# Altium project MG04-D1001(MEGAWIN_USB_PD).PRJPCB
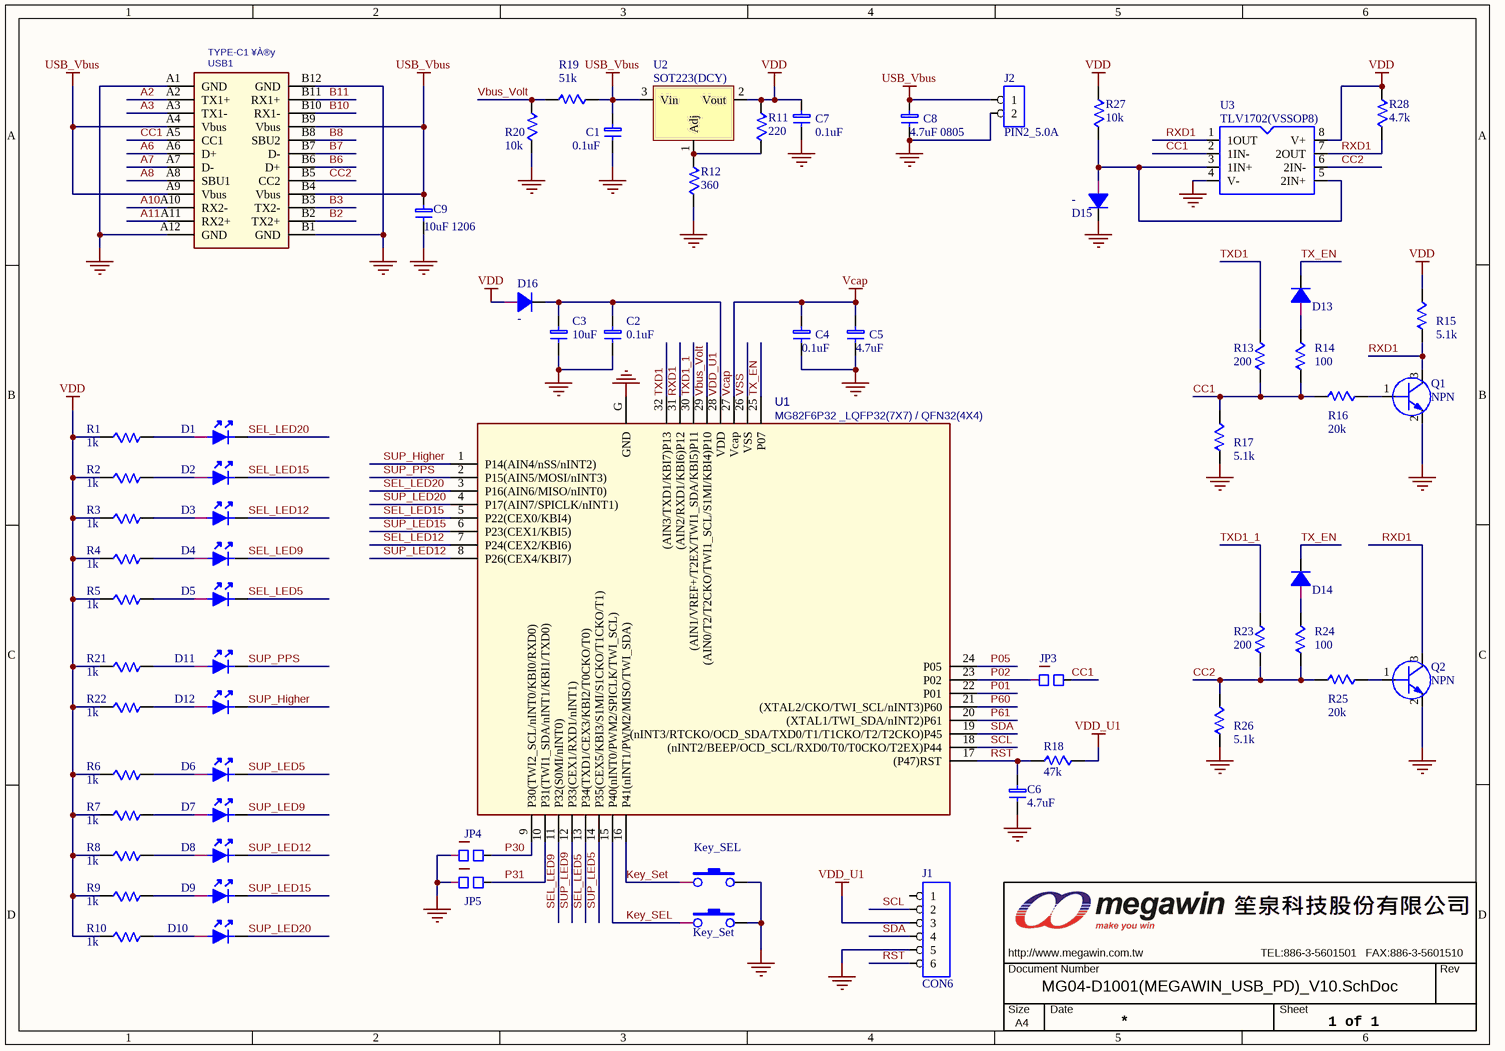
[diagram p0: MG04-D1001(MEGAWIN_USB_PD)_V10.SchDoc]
1 sheet, 67 parts. Net scope: global (net labels, ports and power ports of the same name join across sheets).
Board file: MG04-D1001(MEGAWIN_USB_PD)_V10.PcbDoc

## Sheet MG04-D1001(MEGAWIN_USB_PD)_V10.SchDoc
size 279 x 195 mm

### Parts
C1  0.1uF  [0603C]
C2  0.1uF  [0603C]
C3  10uF  [0603C]
C4  0.1uF  [0603C]
C5  4.7uF  [0603C]
C6  4.7uF  [0603C]
C7  0.1uF  [0603C]
C8  4.7uF 0805  [0805C]
C9  10uF 1206  [1206C]
D1  LED_SC  [0603D]  (value not drawn)
D2  LED_SC  [0603D]  (value not drawn)
D3  LED_SC  [0603D]  (value not drawn)
D4  LED_SC  [0603D]  (value not drawn)
D5  LED_SC  [0603D]  (value not drawn)
D6  LED_SC  [0603D]  (value not drawn)
D7  LED_SC  [0603D]  (value not drawn)
D8  LED_SC  [0603D]  (value not drawn)
D9  LED_SC  [0603D]  (value not drawn)
D10  LED_SC  [0603D]  (value not drawn)
D11  LED_SC  [0603D]  (value not drawn)
D12  LED_SC  [0603D]  (value not drawn)
D13  1N5817  [D4148_SMD]  (value not drawn)
D14  1N5817  [D4148_SMD]  (value not drawn)
D15  -  [D4148_SMD]
D16  -  [D4148_SMD]
J1  CON6  [PS6P254]
J2  PIN2_5.0A  [PIN2_5.0A]
JP3  JUMPER_2  [0603J]  (value not drawn)
JP4  JUMPER_2  [0603J]  (value not drawn)
JP5  JUMPER_2  [0603J]  (value not drawn)
Key_SEL  SW-PB  [SW_T]  (value not drawn)
Key_Set  SW-PB  [SW_T]  (value not drawn)
MW1  OrgAddr3: TEL:886-3-5601501   FAX:886-3-5601510  Page Size: A4  [MEGAWIN_3.4_LOGO]  (hidden comment: MW-A4)  (no BOM)
Q1  NPN  [SOT23]
Q2  NPN  [SOT23]
R1  1k  [0603R]
R2  1k  [0603R]
R3  1k  [0603R]
R4  1k  [0603R]
R5  1k  [0603R]
R6  1k  [0603R]
R7  1k  [0603R]
R8  1k  [0603R]
R9  1k  [0603R]
R10  1k  [0603R]
R11  220  [0603R]
R12  360  [0603R]
R13  200  [0603R]
R14  100  [0603R]
R15  5.1k  [0603R]
R16  20k  [0603R]
R17  5.1k  [0603R]
R18  47k  [0603R]
R19  51k  [0603R]
R20  10k  [0603R]
R21  1k  [0603R]
R22  1k  [0603R]
R23  200  [0603R]
R24  100  [0603R]
R25  20k  [0603R]
R26  5.1k  [0603R]
R27  10k  [0603R]
R28  4.7k  [0603R]
U1  MG82F6P32 _LQFP32(7X7) / QFN32(4X4)  [QFP32_7X7_QFN32_4X4]
U2  SOT223(DCY)  [SOT223]
U3  TLV1702(VSSOP8)  [SO8_120P065]
USB1  TYPE-C1 ¥À®y  [USB24_CF]

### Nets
USB_Vbus: C1.1 C8.1 C9.1 J2.1 R19.2 U2.3(Vin) USB1.A4(Vbus) USB1.A9(Vbus) USB1.B4(Vbus) USB1.B9(Vbus)
Vcap: C4.1 C5.1 U1.27(Vcap)
VDD: C7.1 D16.1(A) R1.2 R2.2 R3.2 R4.2 R5.2 R6.2 R7.2 R8.2 R9.2 R10.2 R11.1 R15.2 R21.2 R22.2 R27.1 R28.1 U2.2(Vout) U3.8(V+)
VDD_U1: C2.1 C3.1 D16.2(K) J1.3 R18.2 U1.28(VDD)
VSS: C1.2 C2.2 C3.2 C4.2 C5.2 C6.2 C7.2 C8.2 C9.2 D15.2(K) J1.5 J2.2 JP4.1 JP5.1 Key_SEL.2 Key_Set.2 Q1.2(E) Q2.2(E) R12.2 R17.1 R20.2 R26.1 U1.26(VSS) U1.G(GND) U3.4(V-) USB1.A1(GND) USB1.A12(GND) USB1.B1(GND) USB1.B12(GND)
A2: USB1.A2(TX1+)
A3: USB1.A3(TX1-)
A6: USB1.A6(D+)
A7: USB1.A7(D-)
A8: USB1.A8(SBU1)
A10: USB1.A10(RX2-)
A11: USB1.A11(RX2+)
B2: USB1.B2(TX2+)
B3: USB1.B3(TX2-)
B6: USB1.B6(D+)
B7: USB1.B7(D-)
B8: USB1.B8(SBU2)
B10: USB1.B10(RX1-)
B11: USB1.B11(RX1+)
CC1: JP3.2 R13.1 R14.1 R16.1 R17.2 U3.2(1IN-) USB1.A5(CC1)
CC2: R23.1 R24.1 R25.1 R26.2 U3.6(2IN-) USB1.B5(CC2)
Key_SEL: Key_Set.1 U1.15(P40(nINT0/PWM2/SPICLK/TWI_SCL))
Key_Set: Key_SEL.1 U1.16(P41(nINT1/PWM2/MISO/TWI_SDA))
P01: U1.22(P01)
P02: JP3.1 U1.23(P02)
P05: U1.24(P05)
P30: JP4.2 U1.9(P30(TWI2_SCL/nINT0/KBI0/RXD0))
P31: JP5.2 U1.10(P31(TWI1_SDA/nINT1/KBI1/TXD0))
P60: U1.21((XTAL2/CKO/TWI_SCL/nINT3)P60)
P61: U1.20((XTAL1/TWI_SDA/nINT2)P61)
RST: C6.1 J1.6 R18.1 U1.17((P47)RST)
RXD1: Q1.3(C) Q2.3(C) R15.1 R28.2 U1.31((AIN2/RXD1/KBI6)P12) U3.1(1OUT) U3.7(2OUT)
SCL: J1.2 U1.18((nINT2/BEEP/OCD_SCL/RXD0/T0/T0CKO/T2EX)P44)
SDA: J1.4 U1.19((nINT3/RTCKO/OCD_SDA/TXD0/T1/T1CKO/T2/T2CKO)P45)
SEL_LED5: D5.2 U1.13(P34(TXD1/CEX3/KBI2/T0CKO/T0))
SEL_LED9: D4.2 U1.11(P32(S0MI/nINT0))
SEL_LED12: D3.2 U1.7(P24(CEX2/KBI6))
SEL_LED15: D2.2 U1.5(P22(CEX0/KBI4))
SEL_LED20: D1.2 U1.3(P16(AIN6/MISO/nINT0))
SUP_Higher: D12.2 U1.1(P14(AIN4/nSS/nINT2))
SUP_LED5: D6.2 U1.14(P35(CEX5/KBI3/S1MI/S1CKO/T1CKO/T1))
SUP_LED9: D7.2 U1.12(P33(CEX1/RXD1/nINT1))
SUP_LED12: D8.2 U1.8(P26(CEX4/KBI7))
SUP_LED15: D9.2 U1.6(P23(CEX1/KBI5))
SUP_LED20: D10.2 U1.4(P17(AIN7/SPICLK/nINT1))
SUP_PPS: D11.2 U1.2(P15(AIN5/MOSI/nINT3))
TX_EN: D13.2(K) D14.2(K) U1.25(P07)
TXD1: R13.2 U1.32((AIN3/TXD1/KBI7)P13)
TXD1_1: R23.2 U1.30((AIN1/VREF+/T2EX/TWI1_SDA/KBI5)P11)
Vbus_Volt: R19.1 R20.1 U1.29((AIN0/T2/T2CKO/TWI1_SCL/S1MI/KBI4)P10)
NetD1_1: D1.1 R1.1
NetD2_1: D2.1 R2.1
NetD3_1: D3.1 R3.1
NetD4_1: D4.1 R4.1
NetD5_1: D5.1 R5.1
NetD6_1: D6.1 R6.1
NetD7_1: D7.1 R7.1
NetD8_1: D8.1 R8.1
NetD9_1: D9.1 R9.1
NetD10_1: D10.1 R10.1
NetD11_1: D11.1 R21.1
NetD12_1: D12.1 R22.1
NetD13_1: D13.1(A) R14.2
NetD14_1: D14.1(A) R24.2
NetD15_1: D15.1(A) R27.2 U3.3(1IN+) U3.5(2IN+)
NetQ1_1: Q1.1(B) R16.2
NetQ2_1: Q2.1(B) R25.2
NetR11_2: R11.2 R12.1 U2.1(Adj)

Not connected (* = marked no-connect by the designer): J1 1

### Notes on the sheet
- 1 of 1

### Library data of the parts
C1-C9 = CAP: Capacitor
D13-D16 = DIODE
J1 = CON6: Connector
J2 = CON2: Connector
JP3-JP5 = JUMPER_2: Jumper
MW1 = MW_A4_1
Q1 Q2 = NPN: NPN Transistor
R1-R28 = RES1
U1 = IC32_MG82FG5C64
U2 = TO220_AOI
U3 = IC8_TLV1702
USB1 = USB TYPE-C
